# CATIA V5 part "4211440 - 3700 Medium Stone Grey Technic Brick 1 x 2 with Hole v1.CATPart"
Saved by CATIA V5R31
Part number: 1x2
Definition: 4211440 - 3700 Medium Stone Grey Technic Brick 1 x 2 with Hole v1
Nomenclature: 4211440 - 3700 Medium Stone Grey Technic Brick 1 x 2 with Hole v1
Source: Unknown
Bounding box of the stored display mesh (mm): x -4 to 12, y 0 to 11.2, z -4 to 4
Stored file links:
  C:\Users\super\Desktop\LEGO\TFG-2621\TFG_02621_anejos\4211440 - 3700 Medium Stone Grey Technic Brick 1 x 2 with Hole v1.CATPart
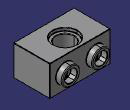
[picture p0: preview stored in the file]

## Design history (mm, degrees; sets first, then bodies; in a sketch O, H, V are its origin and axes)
AxisSystem1: origin (0, 0, 0), X (1, 0, 0), Y (0, 1, 0), Z (0, 0, 1)
Body1 "Body1" (main body)
  Solid1: solid without history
